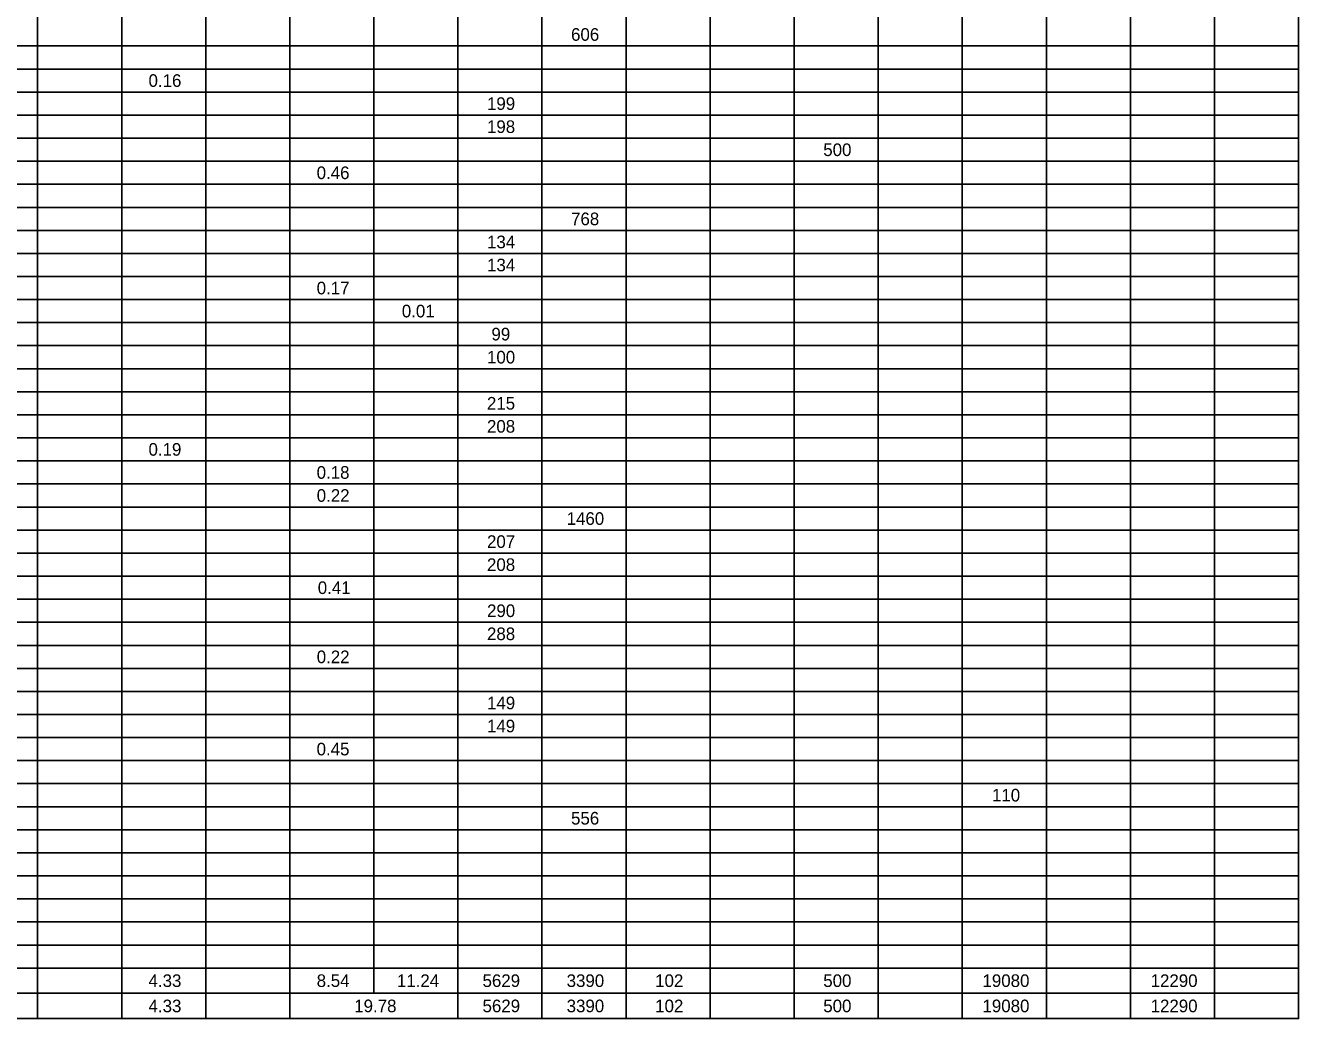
# Model space of a CAD drawing. Extents: x 91011267 to 91022583, y 37007614 to 37014266.
# Drawn here: x 91012044 to 91012802, y 37008895 to 37009486 of the extents above; entities that cross this region are included whole.
import ezdxf

# ---------------------------------------------------------------- set-up
doc = ezdxf.new("R2010")
doc.units = 0
doc.layers.add('SC_Scratch2', color=7, linetype='Continuous')
doc.layers.add('SH_Data', color=7, linetype='Continuous')

msp = doc.modelspace()

# ---------------------------------------------------------------- linework, layer by layer
at = {"layer": 'SC_Scratch2'}
msp.add_lwpolyline([(91011277.35, 37009944.63), (91012802.35, 37009944.63), (91012802.35, 37008894.63), (91011277.35, 37008894.63)], close=True, dxfattribs=at)
at = {"layer": 'SH_Data'}
for p, q in [((91012051.05, 37009570.43), (91012051.05, 37009364.35)), ((91012101.14, 37009570.43), (91012101.14, 37009364.35)), ((91012151.23, 37009570.43), (91012151.23, 37009364.35)), ((91012201.31, 37009570.43), (91012201.31, 37009364.35)), ((91012251.4, 37009570.43), (91012251.4, 37009364.35)), ((91012301.49, 37009570.43), (91012301.49, 37009364.35)), ((91012351.57, 37009570.43), (91012351.57, 37009364.35)), ((91012401.66, 37009570.43), (91012401.66, 37009364.35)), ((91012451.75, 37009570.43), (91012451.75, 37009364.35)), ((91012501.83, 37009570.43), (91012501.83, 37009364.35)), ((91012551.92, 37009570.43), (91012551.92, 37009364.35)), ((91012602, 37009570.43), (91012602, 37009364.35)), ((91012652.09, 37009570.43), (91012652.09, 37009364.35)), ((91012702.18, 37009570.43), (91012702.18, 37009364.35)), ((91012752.26, 37009570.43), (91012752.26, 37009364.35)), ((91012802.35, 37009570.43), (91012802.35, 37009364.35)), ((91012000.97, 37009474.26), (91012551.92, 37009474.26)), ((91012551.92, 37009474.26), (91012602, 37009474.26)), ((91012602, 37009474.26), (91012652.09, 37009474.26)), ((91012652.09, 37009474.26), (91012702.18, 37009474.26)), ((91012702.18, 37009474.26), (91012802.35, 37009474.26)), ((91012000.97, 37009460.52), (91012551.92, 37009460.52)), ((91012551.92, 37009460.52), (91012602, 37009460.52)), ((91012602, 37009460.52), (91012652.09, 37009460.52)), ((91012652.09, 37009460.52), (91012702.18, 37009460.52)), ((91012702.18, 37009460.52), (91012802.35, 37009460.52)), ((91012000.97, 37009446.78), (91012551.92, 37009446.78)), ((91012551.92, 37009446.78), (91012602, 37009446.78)), ((91012602, 37009446.78), (91012652.09, 37009446.78)), ((91012652.09, 37009446.78), (91012702.18, 37009446.78)), ((91012702.18, 37009446.78), (91012802.35, 37009446.78)), ((91012000.97, 37009433.04), (91012551.92, 37009433.04)), ((91012551.92, 37009433.04), (91012602, 37009433.04)), ((91012602, 37009433.04), (91012652.09, 37009433.04)), ((91012652.09, 37009433.04), (91012702.18, 37009433.04)), ((91012702.18, 37009433.04), (91012802.35, 37009433.04)), ((91012000.97, 37009419.31), (91012551.92, 37009419.31)), ((91012551.92, 37009419.31), (91012602, 37009419.31)), ((91012602, 37009419.31), (91012652.09, 37009419.31)), ((91012652.09, 37009419.31), (91012702.18, 37009419.31)), ((91012702.18, 37009419.31), (91012802.35, 37009419.31)), ((91012000.97, 37009405.57), (91012551.92, 37009405.57)), ((91012551.92, 37009405.57), (91012602, 37009405.57)), ((91012602, 37009405.57), (91012652.09, 37009405.57)), ((91012652.09, 37009405.57), (91012702.18, 37009405.57)), ((91012702.18, 37009405.57), (91012802.35, 37009405.57)), ((91012000.97, 37009391.83), (91012551.92, 37009391.83)), ((91012551.92, 37009391.83), (91012602, 37009391.83)), ((91012602, 37009391.83), (91012652.09, 37009391.83)), ((91012652.09, 37009391.83), (91012702.18, 37009391.83)), ((91012702.18, 37009391.83), (91012802.35, 37009391.83)), ((91012000.97, 37009378.09), (91012551.92, 37009378.09)), ((91012551.92, 37009378.09), (91012602, 37009378.09)), ((91012602, 37009378.09), (91012652.09, 37009378.09)), ((91012652.09, 37009378.09), (91012702.18, 37009378.09)), ((91012702.18, 37009378.09), (91012802.35, 37009378.09)), ((91012000.97, 37009364.35), (91012551.92, 37009364.35)), ((91012051.05, 37009364.35), (91012051.05, 37009350.61)), ((91012101.14, 37009364.35), (91012101.14, 37009350.61)), ((91012151.23, 37009364.35), (91012151.23, 37009350.61)), ((91012201.31, 37009364.35), (91012201.31, 37009350.61)), ((91012251.4, 37009364.35), (91012251.4, 37009350.61)), ((91012301.49, 37009364.35), (91012301.49, 37009350.61)), ((91012351.57, 37009364.35), (91012351.57, 37009350.61)), ((91012401.66, 37009364.35), (91012401.66, 37009350.61)), ((91012451.75, 37009364.35), (91012451.75, 37009350.61)), ((91012501.83, 37009364.35), (91012501.83, 37009350.61)), ((91012551.92, 37009364.35), (91012602, 37009364.35)), ((91012551.92, 37009364.35), (91012551.92, 37009350.61)), ((91012602, 37009364.35), (91012652.09, 37009364.35)), ((91012602, 37009364.35), (91012602, 37009350.61)), ((91012652.09, 37009364.35), (91012702.18, 37009364.35)), ((91012652.09, 37009364.35), (91012652.09, 37009350.61)), ((91012702.18, 37009364.35), (91012802.35, 37009364.35)), ((91012702.18, 37009364.35), (91012702.18, 37009350.61)), ((91012752.26, 37009364.35), (91012752.26, 37009350.61)), ((91012802.35, 37009364.35), (91012802.35, 37009350.61)), ((91012000.97, 37009350.61), (91012551.92, 37009350.61)), ((91012051.05, 37009350.61), (91012051.05, 37009336.88)), ((91012101.14, 37009350.61), (91012101.14, 37009336.88)), ((91012151.23, 37009350.61), (91012151.23, 37009336.88)), ((91012201.31, 37009350.61), (91012201.31, 37009336.88)), ((91012251.4, 37009350.61), (91012251.4, 37009336.88)), ((91012301.49, 37009350.61), (91012301.49, 37009336.88)), ((91012351.57, 37009350.61), (91012351.57, 37009336.88)), ((91012401.66, 37009350.61), (91012401.66, 37009336.88)), ((91012451.75, 37009350.61), (91012451.75, 37009336.88)), ((91012501.83, 37009350.61), (91012501.83, 37009336.88)), ((91012551.92, 37009350.61), (91012602, 37009350.61)), ((91012551.92, 37009350.61), (91012551.92, 37009336.88)), ((91012602, 37009350.61), (91012652.09, 37009350.61)), ((91012602, 37009350.61), (91012602, 37009336.88)), ((91012652.09, 37009350.61), (91012702.18, 37009350.61)), ((91012652.09, 37009350.61), (91012652.09, 37009336.88)), ((91012702.18, 37009350.61), (91012802.35, 37009350.61)), ((91012702.18, 37009350.61), (91012702.18, 37009336.88)), ((91012752.26, 37009350.61), (91012752.26, 37009336.88)), ((91012802.35, 37009350.61), (91012802.35, 37009336.88)), ((91012000.97, 37009336.88), (91012551.92, 37009336.88)), ((91012051.05, 37009336.88), (91012051.05, 37009295.66)), ((91012101.14, 37009336.88), (91012101.14, 37009295.66)), ((91012151.23, 37009336.88), (91012151.23, 37009295.66)), ((91012201.31, 37009336.88), (91012201.31, 37009295.66)), ((91012251.4, 37009336.88), (91012251.4, 37009295.66)), ((91012301.49, 37009336.88), (91012301.49, 37009295.66)), ((91012351.57, 37009336.88), (91012351.57, 37009295.66)), ((91012401.66, 37009336.88), (91012401.66, 37009295.66)), ((91012451.75, 37009336.88), (91012451.75, 37009295.66)), ((91012501.83, 37009336.88), (91012501.83, 37009295.66)), ((91012551.92, 37009336.88), (91012602, 37009336.88)), ((91012551.92, 37009336.88), (91012551.92, 37009295.66)), ((91012602, 37009336.88), (91012652.09, 37009336.88)), ((91012602, 37009336.88), (91012602, 37009295.66)), ((91012652.09, 37009336.88), (91012702.18, 37009336.88)), ((91012652.09, 37009336.88), (91012652.09, 37009295.66)), ((91012702.18, 37009336.88), (91012802.35, 37009336.88)), ((91012702.18, 37009336.88), (91012702.18, 37009295.66)), ((91012752.26, 37009336.88), (91012752.26, 37009295.66)), ((91012802.35, 37009336.88), (91012802.35, 37009295.66)), ((91012000.97, 37009323.14), (91012551.92, 37009323.14)), ((91012551.92, 37009323.14), (91012602, 37009323.14)), ((91012602, 37009323.14), (91012652.09, 37009323.14)), ((91012652.09, 37009323.14), (91012702.18, 37009323.14)), ((91012702.18, 37009323.14), (91012802.35, 37009323.14)), ((91012000.97, 37009309.4), (91012551.92, 37009309.4)), ((91012551.92, 37009309.4), (91012602, 37009309.4)), ((91012602, 37009309.4), (91012652.09, 37009309.4)), ((91012652.09, 37009309.4), (91012702.18, 37009309.4)), ((91012702.18, 37009309.4), (91012802.35, 37009309.4)), ((91012000.97, 37009295.66), (91012551.92, 37009295.66)), ((91012051.05, 37009295.66), (91012051.05, 37009281.92)), ((91012101.14, 37009295.66), (91012101.14, 37009281.92)), ((91012151.23, 37009295.66), (91012151.23, 37009281.92)), ((91012201.31, 37009295.66), (91012201.31, 37009281.92)), ((91012251.4, 37009295.66), (91012251.4, 37009281.92)), ((91012301.49, 37009295.66), (91012301.49, 37009281.92)), ((91012351.57, 37009295.66), (91012351.57, 37009281.92)), ((91012401.66, 37009295.66), (91012401.66, 37009281.92)), ((91012451.75, 37009295.66), (91012451.75, 37009281.92)), ((91012501.83, 37009295.66), (91012501.83, 37009281.92)), ((91012551.92, 37009295.66), (91012602, 37009295.66)), ((91012551.92, 37009295.66), (91012551.92, 37009281.92)), ((91012602, 37009295.66), (91012652.09, 37009295.66)), ((91012602, 37009295.66), (91012602, 37009281.92)), ((91012652.09, 37009295.66), (91012702.18, 37009295.66)), ((91012652.09, 37009295.66), (91012652.09, 37009281.92)), ((91012702.18, 37009295.66), (91012802.35, 37009295.66)), ((91012702.18, 37009295.66), (91012702.18, 37009281.92)), ((91012752.26, 37009295.66), (91012752.26, 37009281.92)), ((91012802.35, 37009295.66), (91012802.35, 37009281.92)), ((91012000.97, 37009281.92), (91012551.92, 37009281.92)), ((91012051.05, 37009281.92), (91012051.05, 37009268.18)), ((91012101.14, 37009281.92), (91012101.14, 37009268.18)), ((91012151.23, 37009281.92), (91012151.23, 37009268.18)), ((91012201.31, 37009281.92), (91012201.31, 37009268.18)), ((91012251.4, 37009281.92), (91012251.4, 37009268.18)), ((91012301.49, 37009281.92), (91012301.49, 37009268.18)), ((91012351.57, 37009281.92), (91012351.57, 37009268.18)), ((91012401.66, 37009281.92), (91012401.66, 37009268.18)), ((91012451.75, 37009281.92), (91012451.75, 37009268.18)), ((91012501.83, 37009281.92), (91012501.83, 37009268.18)), ((91012551.92, 37009281.92), (91012602, 37009281.92)), ((91012551.92, 37009281.92), (91012551.92, 37009268.18)), ((91012602, 37009281.92), (91012652.09, 37009281.92)), ((91012602, 37009281.92), (91012602, 37009268.18)), ((91012652.09, 37009281.92), (91012702.18, 37009281.92)), ((91012652.09, 37009281.92), (91012652.09, 37009268.18)), ((91012702.18, 37009281.92), (91012802.35, 37009281.92)), ((91012702.18, 37009281.92), (91012702.18, 37009268.18)), ((91012752.26, 37009281.92), (91012752.26, 37009268.18)), ((91012802.35, 37009281.92), (91012802.35, 37009268.18)), ((91012000.97, 37009268.18), (91012551.92, 37009268.18)), ((91012051.05, 37009268.18), (91012051.05, 37009226.97)), ((91012101.14, 37009268.18), (91012101.14, 37009226.97)), ((91012151.23, 37009268.18), (91012151.23, 37009226.97)), ((91012201.31, 37009268.18), (91012201.31, 37009226.97)), ((91012251.4, 37009268.18), (91012251.4, 37009226.97)), ((91012301.49, 37009268.18), (91012301.49, 37009226.97)), ((91012351.57, 37009268.18), (91012351.57, 37009226.97)), ((91012401.66, 37009268.18), (91012401.66, 37009226.97)), ((91012451.75, 37009268.18), (91012451.75, 37009226.97)), ((91012501.83, 37009268.18), (91012501.83, 37009226.97)), ((91012551.92, 37009268.18), (91012602, 37009268.18)), ((91012551.92, 37009268.18), (91012551.92, 37009226.97)), ((91012602, 37009268.18), (91012652.09, 37009268.18)), ((91012602, 37009268.18), (91012602, 37009226.97)), ((91012652.09, 37009268.18), (91012702.18, 37009268.18)), ((91012652.09, 37009268.18), (91012652.09, 37009226.97)), ((91012702.18, 37009268.18), (91012802.35, 37009268.18)), ((91012702.18, 37009268.18), (91012702.18, 37009226.97)), ((91012752.26, 37009268.18), (91012752.26, 37009226.97)), ((91012802.35, 37009268.18), (91012802.35, 37009226.97)), ((91012000.97, 37009254.45), (91012551.92, 37009254.45)), ((91012551.92, 37009254.45), (91012602, 37009254.45)), ((91012602, 37009254.45), (91012652.09, 37009254.45)), ((91012652.09, 37009254.45), (91012702.18, 37009254.45)), ((91012702.18, 37009254.45), (91012802.35, 37009254.45)), ((91012000.97, 37009240.71), (91012551.92, 37009240.71)), ((91012551.92, 37009240.71), (91012602, 37009240.71)), ((91012602, 37009240.71), (91012652.09, 37009240.71)), ((91012652.09, 37009240.71), (91012702.18, 37009240.71)), ((91012702.18, 37009240.71), (91012802.35, 37009240.71)), ((91012000.97, 37009226.97), (91012551.92, 37009226.97)), ((91012051.05, 37009226.97), (91012051.05, 37009213.23)), ((91012101.14, 37009226.97), (91012101.14, 37009213.23)), ((91012151.23, 37009226.97), (91012151.23, 37009213.23)), ((91012201.31, 37009226.97), (91012201.31, 37009213.23)), ((91012251.4, 37009226.97), (91012251.4, 37009213.23)), ((91012301.49, 37009226.97), (91012301.49, 37009213.23)), ((91012351.57, 37009226.97), (91012351.57, 37009213.23)), ((91012401.66, 37009226.97), (91012401.66, 37009213.23)), ((91012451.75, 37009226.97), (91012451.75, 37009213.23)), ((91012501.83, 37009226.97), (91012501.83, 37009213.23)), ((91012551.92, 37009226.97), (91012602, 37009226.97)), ((91012551.92, 37009226.97), (91012551.92, 37009213.23)), ((91012602, 37009226.97), (91012652.09, 37009226.97)), ((91012602, 37009226.97), (91012602, 37009213.23)), ((91012652.09, 37009226.97), (91012702.18, 37009226.97)), ((91012652.09, 37009226.97), (91012652.09, 37009213.23)), ((91012702.18, 37009226.97), (91012802.35, 37009226.97)), ((91012702.18, 37009226.97), (91012702.18, 37009213.23)), ((91012752.26, 37009226.97), (91012752.26, 37009213.23)), ((91012802.35, 37009226.97), (91012802.35, 37009213.23)), ((91012000.97, 37009213.23), (91012551.92, 37009213.23)), ((91012051.05, 37009213.23), (91012051.05, 37009199.49)), ((91012101.14, 37009213.23), (91012101.14, 37009199.49)), ((91012151.23, 37009213.23), (91012151.23, 37009199.49)), ((91012201.31, 37009213.23), (91012201.31, 37009199.49)), ((91012251.4, 37009213.23), (91012251.4, 37009199.49)), ((91012301.49, 37009213.23), (91012301.49, 37009199.49)), ((91012351.57, 37009213.23), (91012351.57, 37009199.49)), ((91012401.66, 37009213.23), (91012401.66, 37009199.49)), ((91012451.75, 37009213.23), (91012451.75, 37009199.49)), ((91012501.83, 37009213.23), (91012501.83, 37009199.49)), ((91012551.92, 37009213.23), (91012602, 37009213.23)), ((91012551.92, 37009213.23), (91012551.92, 37009199.49)), ((91012602, 37009213.23), (91012652.09, 37009213.23)), ((91012602, 37009213.23), (91012602, 37009199.49)), ((91012652.09, 37009213.23), (91012702.18, 37009213.23)), ((91012652.09, 37009213.23), (91012652.09, 37009199.49)), ((91012702.18, 37009213.23), (91012802.35, 37009213.23)), ((91012702.18, 37009213.23), (91012702.18, 37009199.49)), ((91012752.26, 37009213.23), (91012752.26, 37009199.49)), ((91012802.35, 37009213.23), (91012802.35, 37009199.49)), ((91012000.97, 37009199.49), (91012551.92, 37009199.49)), ((91012051.05, 37009199.49), (91012051.05, 37008894.63)), ((91012101.14, 37009199.49), (91012101.14, 37008894.63)), ((91012151.23, 37009199.49), (91012151.23, 37008894.63)), ((91012201.31, 37009199.49), (91012201.31, 37008894.63)), ((91012251.4, 37009199.49), (91012251.4, 37008909.68)), ((91012301.49, 37009199.49), (91012301.49, 37008894.63)), ((91012351.57, 37009199.49), (91012351.57, 37008894.63)), ((91012401.66, 37009199.49), (91012401.66, 37008894.63)), ((91012451.75, 37009199.49), (91012451.75, 37008894.63)), ((91012501.83, 37009199.49), (91012501.83, 37008894.63)), ((91012551.92, 37009199.49), (91012602, 37009199.49)), ((91012551.92, 37009199.49), (91012551.92, 37008894.63)), ((91012602, 37009199.49), (91012652.09, 37009199.49)), ((91012602, 37009199.49), (91012602, 37008894.63)), ((91012652.09, 37009199.49), (91012702.18, 37009199.49)), ((91012652.09, 37009199.49), (91012652.09, 37008894.63)), ((91012702.18, 37009199.49), (91012802.35, 37009199.49)), ((91012702.18, 37009199.49), (91012702.18, 37008894.63)), ((91012752.26, 37009199.49), (91012752.26, 37008894.63)), ((91012802.35, 37009199.49), (91012802.35, 37008894.63)), ((91012000.97, 37009185.75), (91012551.92, 37009185.75)), ((91012551.92, 37009185.75), (91012602, 37009185.75)), ((91012602, 37009185.75), (91012652.09, 37009185.75)), ((91012652.09, 37009185.75), (91012702.18, 37009185.75)), ((91012702.18, 37009185.75), (91012802.35, 37009185.75)), ((91012000.97, 37009172.02), (91012551.92, 37009172.02)), ((91012551.92, 37009172.02), (91012602, 37009172.02)), ((91012602, 37009172.02), (91012652.09, 37009172.02)), ((91012652.09, 37009172.02), (91012702.18, 37009172.02)), ((91012702.18, 37009172.02), (91012802.35, 37009172.02)), ((91012000.97, 37009158.28), (91012551.92, 37009158.28)), ((91012551.92, 37009158.28), (91012602, 37009158.28)), ((91012602, 37009158.28), (91012652.09, 37009158.28)), ((91012652.09, 37009158.28), (91012702.18, 37009158.28)), ((91012702.18, 37009158.28), (91012802.35, 37009158.28)), ((91012000.97, 37009144.54), (91012551.92, 37009144.54)), ((91012551.92, 37009144.54), (91012602, 37009144.54)), ((91012602, 37009144.54), (91012652.09, 37009144.54)), ((91012652.09, 37009144.54), (91012702.18, 37009144.54)), ((91012702.18, 37009144.54), (91012802.35, 37009144.54)), ((91012000.97, 37009130.8), (91012551.92, 37009130.8)), ((91012551.92, 37009130.8), (91012602, 37009130.8)), ((91012602, 37009130.8), (91012652.09, 37009130.8)), ((91012652.09, 37009130.8), (91012702.18, 37009130.8)), ((91012702.18, 37009130.8), (91012802.35, 37009130.8)), ((91012000.97, 37009117.06), (91012551.92, 37009117.06)), ((91012551.92, 37009117.06), (91012602, 37009117.06)), ((91012602, 37009117.06), (91012652.09, 37009117.06)), ((91012652.09, 37009117.06), (91012702.18, 37009117.06)), ((91012702.18, 37009117.06), (91012802.35, 37009117.06)), ((91012000.97, 37009103.32), (91012551.92, 37009103.32)), ((91012551.92, 37009103.32), (91012602, 37009103.32)), ((91012602, 37009103.32), (91012652.09, 37009103.32)), ((91012652.09, 37009103.32), (91012702.18, 37009103.32)), ((91012702.18, 37009103.32), (91012802.35, 37009103.32)), ((91012000.97, 37009089.59), (91012551.92, 37009089.59)), ((91012551.92, 37009089.59), (91012602, 37009089.59)), ((91012602, 37009089.59), (91012652.09, 37009089.59)), ((91012652.09, 37009089.59), (91012702.18, 37009089.59)), ((91012702.18, 37009089.59), (91012802.35, 37009089.59)), ((91012000.97, 37009075.85), (91012551.92, 37009075.85)), ((91012551.92, 37009075.85), (91012602, 37009075.85)), ((91012602, 37009075.85), (91012652.09, 37009075.85)), ((91012652.09, 37009075.85), (91012702.18, 37009075.85)), ((91012702.18, 37009075.85), (91012802.35, 37009075.85)), ((91012000.97, 37009062.11), (91012551.92, 37009062.11)), ((91012551.92, 37009062.11), (91012602, 37009062.11)), ((91012602, 37009062.11), (91012652.09, 37009062.11)), ((91012652.09, 37009062.11), (91012702.18, 37009062.11)), ((91012702.18, 37009062.11), (91012802.35, 37009062.11)), ((91012000.97, 37009048.37), (91012551.92, 37009048.37)), ((91012551.92, 37009048.37), (91012602, 37009048.37)), ((91012602, 37009048.37), (91012652.09, 37009048.37)), ((91012652.09, 37009048.37), (91012702.18, 37009048.37)), ((91012702.18, 37009048.37), (91012802.35, 37009048.37)), ((91012000.97, 37009034.63), (91012551.92, 37009034.63)), ((91012551.92, 37009034.63), (91012602, 37009034.63)), ((91012602, 37009034.63), (91012652.09, 37009034.63)), ((91012652.09, 37009034.63), (91012702.18, 37009034.63)), ((91012702.18, 37009034.63), (91012802.35, 37009034.63)), ((91012000.97, 37009020.89), (91012551.92, 37009020.89)), ((91012551.92, 37009020.89), (91012602, 37009020.89)), ((91012602, 37009020.89), (91012652.09, 37009020.89)), ((91012652.09, 37009020.89), (91012702.18, 37009020.89)), ((91012702.18, 37009020.89), (91012802.35, 37009020.89)), ((91012000.97, 37009007.16), (91012551.92, 37009007.16)), ((91012551.92, 37009007.16), (91012602, 37009007.16)), ((91012602, 37009007.16), (91012652.09, 37009007.16)), ((91012652.09, 37009007.16), (91012702.18, 37009007.16)), ((91012702.18, 37009007.16), (91012802.35, 37009007.16)), ((91012000.97, 37008993.42), (91012551.92, 37008993.42)), ((91012551.92, 37008993.42), (91012602, 37008993.42)), ((91012602, 37008993.42), (91012652.09, 37008993.42)), ((91012652.09, 37008993.42), (91012702.18, 37008993.42)), ((91012702.18, 37008993.42), (91012802.35, 37008993.42)), ((91012000.97, 37008979.68), (91012551.92, 37008979.68)), ((91012551.92, 37008979.68), (91012602, 37008979.68)), ((91012602, 37008979.68), (91012652.09, 37008979.68)), ((91012652.09, 37008979.68), (91012702.18, 37008979.68)), ((91012702.18, 37008979.68), (91012802.35, 37008979.68)), ((91012000.97, 37008965.94), (91012551.92, 37008965.94)), ((91012551.92, 37008965.94), (91012602, 37008965.94)), ((91012602, 37008965.94), (91012652.09, 37008965.94)), ((91012652.09, 37008965.94), (91012702.18, 37008965.94)), ((91012702.18, 37008965.94), (91012802.35, 37008965.94)), ((91012000.97, 37008952.2), (91012551.92, 37008952.2)), ((91012551.92, 37008952.2), (91012602, 37008952.2)), ((91012602, 37008952.2), (91012652.09, 37008952.2)), ((91012652.09, 37008952.2), (91012702.18, 37008952.2)), ((91012702.18, 37008952.2), (91012802.35, 37008952.2)), ((91012000.97, 37008938.46), (91012551.92, 37008938.46)), ((91012551.92, 37008938.46), (91012602, 37008938.46)), ((91012602, 37008938.46), (91012652.09, 37008938.46)), ((91012652.09, 37008938.46), (91012702.18, 37008938.46)), ((91012702.18, 37008938.46), (91012802.35, 37008938.46)), ((91012000.97, 37008924.73), (91012551.92, 37008924.73)), ((91012551.92, 37008924.73), (91012602, 37008924.73)), ((91012602, 37008924.73), (91012652.09, 37008924.73)), ((91012652.09, 37008924.73), (91012702.18, 37008924.73)), ((91012702.18, 37008924.73), (91012802.35, 37008924.73)), ((91012000.97, 37008909.68), (91012551.92, 37008909.68)), ((91012551.92, 37008909.68), (91012602, 37008909.68)), ((91012602, 37008909.68), (91012652.09, 37008909.68)), ((91012652.09, 37008909.68), (91012702.18, 37008909.68)), ((91012702.18, 37008909.68), (91012802.35, 37008909.68)), ((91012000.97, 37008894.63), (91012551.92, 37008894.63)), ((91012551.92, 37008894.63), (91012602, 37008894.63)), ((91012602, 37008894.63), (91012652.09, 37008894.63)), ((91012652.09, 37008894.63), (91012702.18, 37008894.63)), ((91012702.18, 37008894.63), (91012802.35, 37008894.63))]:
    msp.add_line(p, q, dxfattribs=at)

# ---------------------------------------------------------------- texts
for s, p in [('606', (91012368.88, 37009477.37)), ('0.16', (91012117.13, 37009449.89)), ('199', (91012318.79, 37009436.15)), ('198', (91012318.79, 37009422.41)), ('500', (91012519.16, 37009408.67)), ('0.46', (91012217.3, 37009394.94)), ('768', (91012368.88, 37009367.46)), ('134', (91012318.81, 37009353.72)), ('134', (91012318.81, 37009339.98)), ('0.17', (91012217.3, 37009326.24)), ('0.01', (91012268.05, 37009312.51)), ('99', (91012321.44, 37009298.77)), ('100', (91012318.81, 37009285.03)), ('215', (91012318.77, 37009257.55)), ('208', (91012318.79, 37009243.81)), ('0.19', (91012117.12, 37009230.08)), ('0.18', (91012217.3, 37009216.34)), ('0.22', (91012217.34, 37009202.6)), ('1460', (91012366.25, 37009188.86)), ('207', (91012318.8, 37009175.12)), ('208', (91012318.79, 37009161.38)), ('0.41', (91012217.96, 37009147.65)), ('290', (91012318.81, 37009133.91)), ('288', (91012318.79, 37009120.17)), ('0.22', (91012217.34, 37009106.43)), ('149', (91012318.79, 37009078.95)), ('149', (91012318.79, 37009065.22)), ('0.45', (91012217.28, 37009051.48)), ('110', (91012619.68, 37009024)), ('556', (91012368.88, 37009010.26)), ('4.33', (91012117.13, 37008913.44)), ('8.54', (91012217.32, 37008913.44)), ('11.24', (91012265.11, 37008913.44)), ('5629', (91012316.14, 37008913.44)), ('3390', (91012366.25, 37008913.44)), ('102', (91012419.01, 37008913.44)), ('500', (91012519.16, 37008913.44)), ('19080', (91012614.03, 37008913.44)), ('12290', (91012714.21, 37008913.44)), ('4.33', (91012117.13, 37008898.39)), ('19.78', (91012239.69, 37008898.39)), ('5629', (91012316.14, 37008898.39)), ('3390', (91012366.25, 37008898.39)), ('102', (91012419.01, 37008898.39)), ('500', (91012519.16, 37008898.39)), ('19080', (91012614.03, 37008898.39)), ('12290', (91012714.21, 37008898.39))]:
    msp.add_text(s, height=7.523, dxfattribs=at).set_placement(p)

doc.saveas('drawing.dxf')
